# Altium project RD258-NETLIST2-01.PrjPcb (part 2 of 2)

## Sheet 9.SchDoc
size 420 x 297 mm
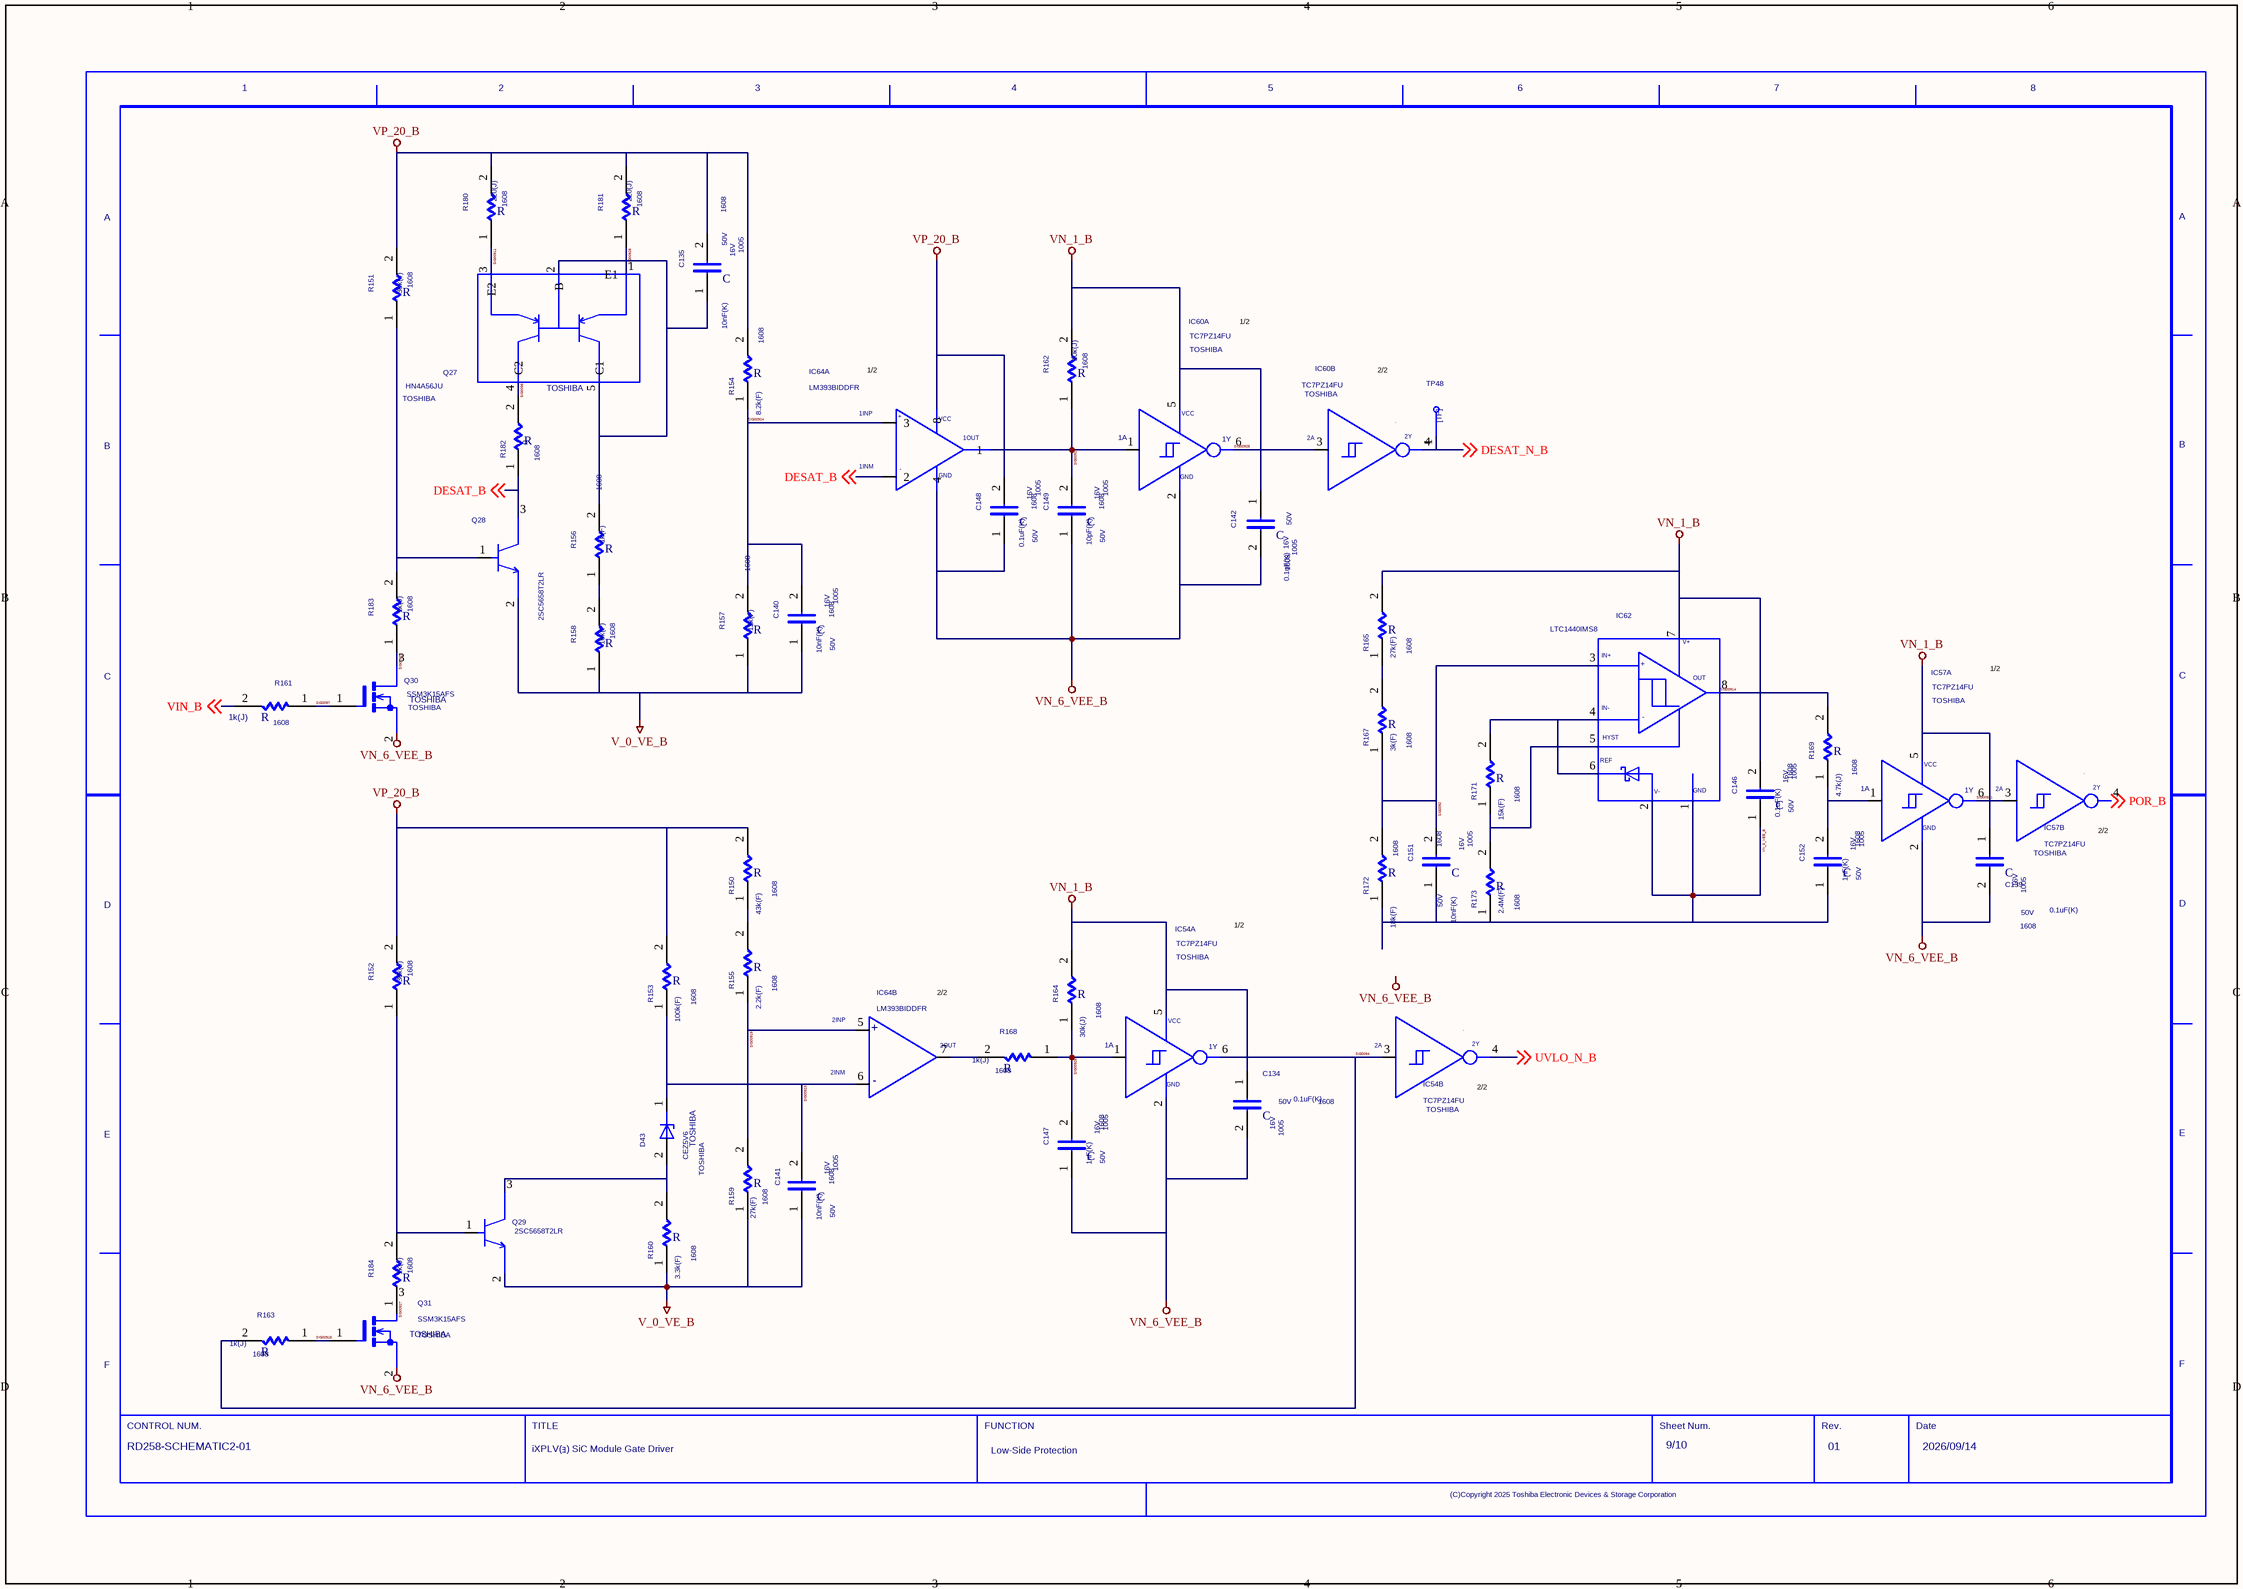
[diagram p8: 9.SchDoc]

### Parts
(Parts that share a designator on the sheet are numbered #1, #2 ... from top to bottom, then left to right.)
C134  VAL1: 0.1uF(K)  CODE: 1005  VOLTAGE: 16V  SIZECODESMD: 1608  VAL2: 50V  (hidden comment: C)
C135  VAL1: 10nF(K)  CODE: 1005  VOLTAGE: 16V  SIZECODESMD: 1608  VAL2: 50V  (hidden comment: C)
C139  VAL1: 0.1uF(K)  CODE: 1005  VOLTAGE: 16V  SIZECODESMD: 1608  VAL2: 50V  (hidden comment: C)
C140  VAL1: 10nF(K)  CODE: 1005  VOLTAGE: 16V  SIZECODESMD: 1608  VAL2: 50V  (hidden comment: C)
C141  VAL1: 10nF(K)  CODE: 1005  VOLTAGE: 16V  SIZECODESMD: 1608  VAL2: 50V  (hidden comment: C)
C142  VAL1: 0.1uF(K)  CODE: 1005  VOLTAGE: 16V  SIZECODESMD: 1608  VAL2: 50V  (hidden comment: C)
C146  VAL1: 0.1uF(K)  CODE: 1005  VOLTAGE: 16V  SIZECODESMD: 1608  VAL2: 50V  (hidden comment: C)
C147  VAL1: 1nF(K)  CODE: 1005  VOLTAGE: 16V  SIZECODESMD: 1608  VAL2: 50V  (hidden comment: C)
C148  VAL1: 0.1uF(K)  CODE: 1005  VOLTAGE: 16V  SIZECODESMD: 1608  VAL2: 50V  (hidden comment: C)
C149  VAL1: 10pF(K)  CODE: 1005  VOLTAGE: 16V  SIZECODESMD: 1608  VAL2: 50V  (hidden comment: C)
C151  VAL1: 10nF(K)  CODE: 1005  VOLTAGE: 16V  SIZECODESMD: 1608  VAL2: 50V  (hidden comment: C)
C152  VAL1: 1nF(K)  CODE: 1005  VOLTAGE: 16V  SIZECODESMD: 1608  VAL2: 50V  (hidden comment: C)
D43  VENDOR: TOSHIBA  (hidden comment: CEZ5V6)
IC54  USERCOMPTEXT3: TOSHIBA  VAL3: TC7PZ14FU  (hidden comment: TC7PZ17FU)  (parts A,B of 2)
IC57  USERCOMPTEXT3: TOSHIBA  VAL3: TC7PZ14FU  (hidden comment: TC7PZ17FU)  (parts A,B of 2)
IC60  USERCOMPTEXT3: TOSHIBA  VAL3: TC7PZ14FU  (hidden comment: TC7PZ17FU)  (parts A,B of 2)
IC62  VAL3: LTC1440IMS8  (hidden comment: LTC1440IS8)
IC64  VAL3: LM393BIDDFR  (hidden comment: LM393B_2)  (parts A,B of 2)
Q27  VENDOR: TOSHIBA  (hidden comment: HN4A56JU)
Q28  VAL3: 2SC5658T2LR  (hidden comment: 2SC5658J)
Q29  VAL3: 2SC5658T2LR  (hidden comment: 2SC5658J)
Q30  VENDOR: TOSHIBA  (hidden comment: SSM3K15AFS)
Q31  VENDOR: TOSHIBA  (hidden comment: SSM3K15AFS)
R150  VAL1: 43k(F)  SIZECODESMD: 1608  (hidden comment: R)
R151  VAL1: 30k(J)  SIZECODESMD: 1608  (hidden comment: R)
R152  VAL1: 30k(J)  SIZECODESMD: 1608  (hidden comment: R)
R153  VAL1: 100k(F)  SIZECODESMD: 1608  (hidden comment: R)
R154  VAL1: 8.2k(F)  SIZECODESMD: 1608  (hidden comment: R)
R155  VAL1: 2.2k(F)  SIZECODESMD: 1608  (hidden comment: R)
R156  VAL1: 1k(F)  SIZECODESMD: 1608  (hidden comment: R)
R157  VAL1: 12k(F)  SIZECODESMD: 1608  (hidden comment: R)
R158  VAL1: 10k(F)  SIZECODESMD: 1608  (hidden comment: R)
R159  VAL1: 27k(F)  SIZECODESMD: 1608  (hidden comment: R)
R160  VAL1: 3.3k(F)  SIZECODESMD: 1608  (hidden comment: R)
R161  VAL1: 1k(J)  SIZECODESMD: 1608  (hidden comment: R)
R162  VAL1: 30k(J)  SIZECODESMD: 1608  (hidden comment: R)
R163  VAL1: 1k(J)  SIZECODESMD: 1608  (hidden comment: R)
R164  VAL1: 30k(J)  SIZECODESMD: 1608  (hidden comment: R)
R165  VAL1: 27k(F)  SIZECODESMD: 1608  (hidden comment: R)
R167  VAL1: 3k(F)  SIZECODESMD: 1608  (hidden comment: R)
R168  VAL1: 1k(J)  SIZECODESMD: 1608  (hidden comment: R)
R169  VAL1: 4.7k(J)  SIZECODESMD: 1608  (hidden comment: R)
R171  VAL1: 15k(F)  SIZECODESMD: 1608  (hidden comment: R)
R172  VAL1: 18k(F)  SIZECODESMD: 1608  (hidden comment: R)
R173  VAL1: 2.4M(F)  SIZECODESMD: 1608  (hidden comment: R)
R180  VAL1: 220(J)  SIZECODESMD: 1608  (hidden comment: R)
R181  VAL1: 220(J)  SIZECODESMD: 1608  (hidden comment: R)
R182  VAL1: 0  SIZECODESMD: 1608  (hidden comment: R)
R183  VAL1: 1k(J)  SIZECODESMD: 1608  (hidden comment: R)
R184  VAL1: 1k(J)  SIZECODESMD: 1608  (hidden comment: R)
TP48  TP  (value not drawn)
U?#9  DATE: 2026/09/14  DRAWINGNUMBER: RD258-SCHEMATIC2-01  TITLE: iXPLV(ｮ) SiC Module Gate Driver  FUNCTION: Low-Side Protection  SHEETNUMBER: 9/10  REVISION: 01  (hidden comment: WAKU_DEF100)

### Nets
V_0_VE_B: C140.1 C141.1 Q28.2(E) Q29.2(E) R157.1 R158.1 R159.1 R160.1
VN_1_B: C134.1 C139.1 C142.1 C146.2 IC54.5 IC57.5 IC60.5 IC62.7(V+) R162.2 R164.2 R165.2
VN_6_VEE_B: C134.2 C139.2 C142.2 C146.1 C147.1 C148.1 C149.1 C151.1 C152.1 IC54.2 IC57.2 IC60.2 IC62.1(GND) IC62.2(V-) IC64.4 Q30.2(S) Q31.2(S) R172.1 R173.1
VP_20_B: C135.2 C148.2 IC64.8 R150.2 R151.2 R152.2 R153.2 R154.2 R180.2 R181.2
DESAT_B: IC64.2 Q28.3(C) R182.1 ; off-sheet DESAT_B
DESAT_N_B: IC60.4 TP48.1 ; off-sheet DESAT_N_B
POR_B: IC57.4 ; off-sheet POR_B
SIG0091: C149.2 IC60.1 IC64.1 R162.1
SIG0092: C151.2 IC62.3(IN+) R167.1 R172.2
SIG0093: Q29.1(B) R152.1 R184.2
SIG0094: IC54.3 IC54.6 R163.2
SIG0095: IC64.7 R168.2
SIG0096: Q27.4(C2) R182.2
SIG0097: Q30.1(G) R161.1
SIG0098: IC62.4(IN-) IC62.6(REF) R171.2
SIG0099: R165.1 R167.2
SIG00910: Q28.1(B) R151.1 R183.2
SIG00911: Q27.3(E2) R180.1
SIG00912: IC62.5(HYST) R171.1 R173.2
SIG00913: D43.2(A) Q29.3(C) R160.2
SIG00914: IC62.8(OUT) R169.2
SIG00915: Q31.1(G) R163.1
SIG00916: R156.1 R158.2
SIG00917: C135.1 Q27.2(B) Q27.5(C1) R156.2
SIG00918: R150.1 R155.2
SIG00919: IC64.5 R155.1 R159.2
SIG00920: C152.2 IC57.1 R169.1
SIG00921: IC57.3 IC57.6
SIG00922: Q30.3(D) R183.1
SIG00923: C141.2 D43.1(C) IC64.6 R153.1
SIG00924: C140.2 IC64.3 R154.1 R157.2
SIG00925: IC60.3 IC60.6
SIG00926: C147.2 IC54.1 R164.1 R168.1
SIG00927: Q31.3(D) R184.1
SIG00928: Q27.1(E1) R181.1
UVLO_N_B: IC54.4 ; off-sheet UVLO_N_B
VIN_B: R161.2 ; off-sheet VIN_B

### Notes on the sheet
- 1/2
- (near IC64) 1/2
- 2/2
- (near IC57) 2/2
- (near IC64) 2/2
- (near IC54) 2/2
- Labels drawn without touching a wire or pin: VN_6_VEE_B

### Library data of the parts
C134 C135 C139-C142 C146-C149 C151 C152 = C: TIME: 08:48:12; UPDATEUSER: HP_Z8_KEYSHOT; SAVECOUNT: 2; TC1: 0; PSPICETEMPLATE: C^@REFDES %1 %2 ?TOLERANCE¦C^@REFDES¦ @VALUE ?IC/IC=@IC/ TC=@TC1,@TC2 ?TOLERANCE¦\n.model C^@REFDES CAP C=1 DEV=@TOLERANCE% TC1=@TC1 TC2=@TC2 VC1=@VC1 VC2=@VC2¦; ORIGINALSYMBOLORIGIN: (0,0); INSTANCENAME: INS2265204
D43 = CEZ5V6: TIME: 14:49:55; UPDATEUSER: fukuda-y; UPDATETIME: 08:16:22; SAVECOUNT: 9; SAVEAREA0: -4630,-153,17114,13055; PSPICETEMPLATE: X^@REFDES %C %A @MODEL; ORIGINALSYMBOLORIGIN: (0,0); INSTANCENAME: INS2265024
IC54 IC57 = TC7PZ14FU_2: TIME: 11:55:01; UPDATEUSER: t5459927; UPDATETIME: 19:09:34; SAVECOUNT: 7; SPLIT_INST: TRUE; PSPICETEMPLATE: X^@REFDES %1A %GND %2A %2Y %VCC %1Y @MODEL; SWAP_INFO: (S1+S2); OriginalSymbolOrigin: (5080,15240); CaptureCellPackProp: TC7PZ14FU_2A; FUNCN: TC7PZ14FU_1; INSTANCENAME: INS2254016
IC60 = TC7PZ14FU_2: TIME: 11:55:01; UPDATEUSER: t5459927; UPDATETIME: 19:09:34; SAVECOUNT: 7; SPLIT_INST: TRUE; PSPICETEMPLATE: X^@REFDES %1A %GND %2A %2Y %VCC %1Y @MODEL; SWAP_INFO: (S1+S2); OriginalSymbolOrigin: (5080,15240); CaptureCellPackProp: TC7PZ14FU_2A; FUNCN: TC7PZ17FU_1; INSTANCENAME: INS2254016
IC62 = LTC1440IS8: TIME: 08:48:16; UPDATEUSER: t5459927; UPDATETIME: 17:22:21; SAVECOUNT: 4; PSPICETEMPLATE: X^@REFDES %GND %V- %IN+ %IN- %HYST %REF %V+ %OUT @MODEL; OriginalSymbolOrigin: (0,0); INSTANCENAME: INS2264292
IC64 = LM393B_2: TIME: 08:48:12; UPDATEUSER: t5459927; UPDATETIME: 19:15:42; SAVECOUNT: 5; SPLIT_INST: TRUE; PSPICETEMPLATE: X^@REFDES %INN %VSS %INP %OUT %VDD @MODEL; COMP: LM393B; VENDOR: TI; SWAP_INFO: (S1+S2); OriginalSymbolOrigin: (2540,0); CaptureCellPackProp: LM393B_2A; FUNCN: LM393B_1; INSTANCENAME: INS2264892
Q27 = HN4A56JU: TIME: 08:48:13; UPDATEUSER: HP_Z8_KEYSHOT; SAVECOUNT: 2; PSPICETEMPLATE: X^@REFDES %B1 %E %B2 %C2 %C1 @MODEL; OriginalSymbolOrigin: (0,0); INSTANCENAME: INS2265108
Q28 = 2SC5658J: TIME: 09:39:04; UPDATEUSER: 19910145; UPDATETIME: 15:12:10; SAVECOUNT: 8; VENDOR: ROHM; SAVEAREA0: -6194,-158,18648,15662; PSPICETEMPLATE: X^@REFDES %C %B %E @MODEL; ORIGINALSYMBOLORIGIN: (0,0); INSTANCENAME: INS2264212
Q29 = 2SC5658J: TIME: 09:39:04; UPDATEUSER: 19910145; UPDATETIME: 15:12:10; SAVECOUNT: 8; VENDOR: ROHM; SAVEAREA0: -6194,-158,18648,15662; PSPICETEMPLATE: X^@REFDES %C %B %E @MODEL; ORIGINALSYMBOLORIGIN: (0,0); INSTANCENAME: INS2264508
Q30 = SSM3K15AFS: TIME: 08:48:15; UPDATEUSER: HP_Z8_KEYSHOT; SAVECOUNT: 2; ORIGINALSYMBOLORIGIN: (0,0); PSPICETEMPLATE: X^@REFDES %D %G %S @MODEL; INSTANCENAME: INS2265300
Q31 = SSM3K15AFS: TIME: 08:48:15; UPDATEUSER: HP_Z8_KEYSHOT; SAVECOUNT: 2; ORIGINALSYMBOLORIGIN: (0,0); PSPICETEMPLATE: X^@REFDES %D %G %S @MODEL; INSTANCENAME: INS2264184
R150-R165 R167-R169 R171-R173 R180 R181 R183 R184 = R: TIME: 08:48:13; UPDATEUSER: HP_Z8_KEYSHOT; SAVECOUNT: 2; VAL2: 100mW; TC1: 0; PSPICETEMPLATE: R^@REFDES %1 %2 ?TOLERANCE¦R^@REFDES¦ @VALUE TC=@TC1,@TC2 ?TOLERANCE¦\n.model R^@REFDES RES R=1 DEV=@TOLERANCE% TC1=@TC1 TC2=@TC2¦; ORIGINALSYMBOLORIGIN: (0,0); INSTANCENAME: INS2263832
R182 = R: TIME: 08:48:13; UPDATEUSER: HP_Z8_KEYSHOT; SAVECOUNT: 2; VAL2: 0.125; PSPICETEMPLATE: R^@REFDES %1 %2 ?TOLERANCE¦R^@REFDES¦ @VALUE TC=@TC1,@TC2 ?TOLERANCE¦\n.model R^@REFDES RES R=1 DEV=@TOLERANCE% TC1=@TC1 TC2=@TC2¦; ORIGINALSYMBOLORIGIN: (0,0); INSTANCENAME: INS2264424
TP48 = TP: TIME: 16:12:21; UPDATEUSER: fukuda-y; UPDATETIME: 16:18:11; SAVECOUNT: 2; SAVEAREA0: -242,-92,12810,7836; ORIGINALSYMBOLORIGIN: (0,0); INSTANCENAME: INS2264820
U?#9 = WAKU_DEF100: PLOTTIME: HH:MM; SAVEAREA0: -63393,-16950,474261,314592; TIME: 14:30:25; UPDATEUSER: t5459927; UPDATETIME: 14:59:41; SAVECOUNT: 4; OriginalSymbolOrigin: (10160,284480); SHTSAVECOUNT: 27

## Sheet 10.SchDoc
size 420 x 297 mm
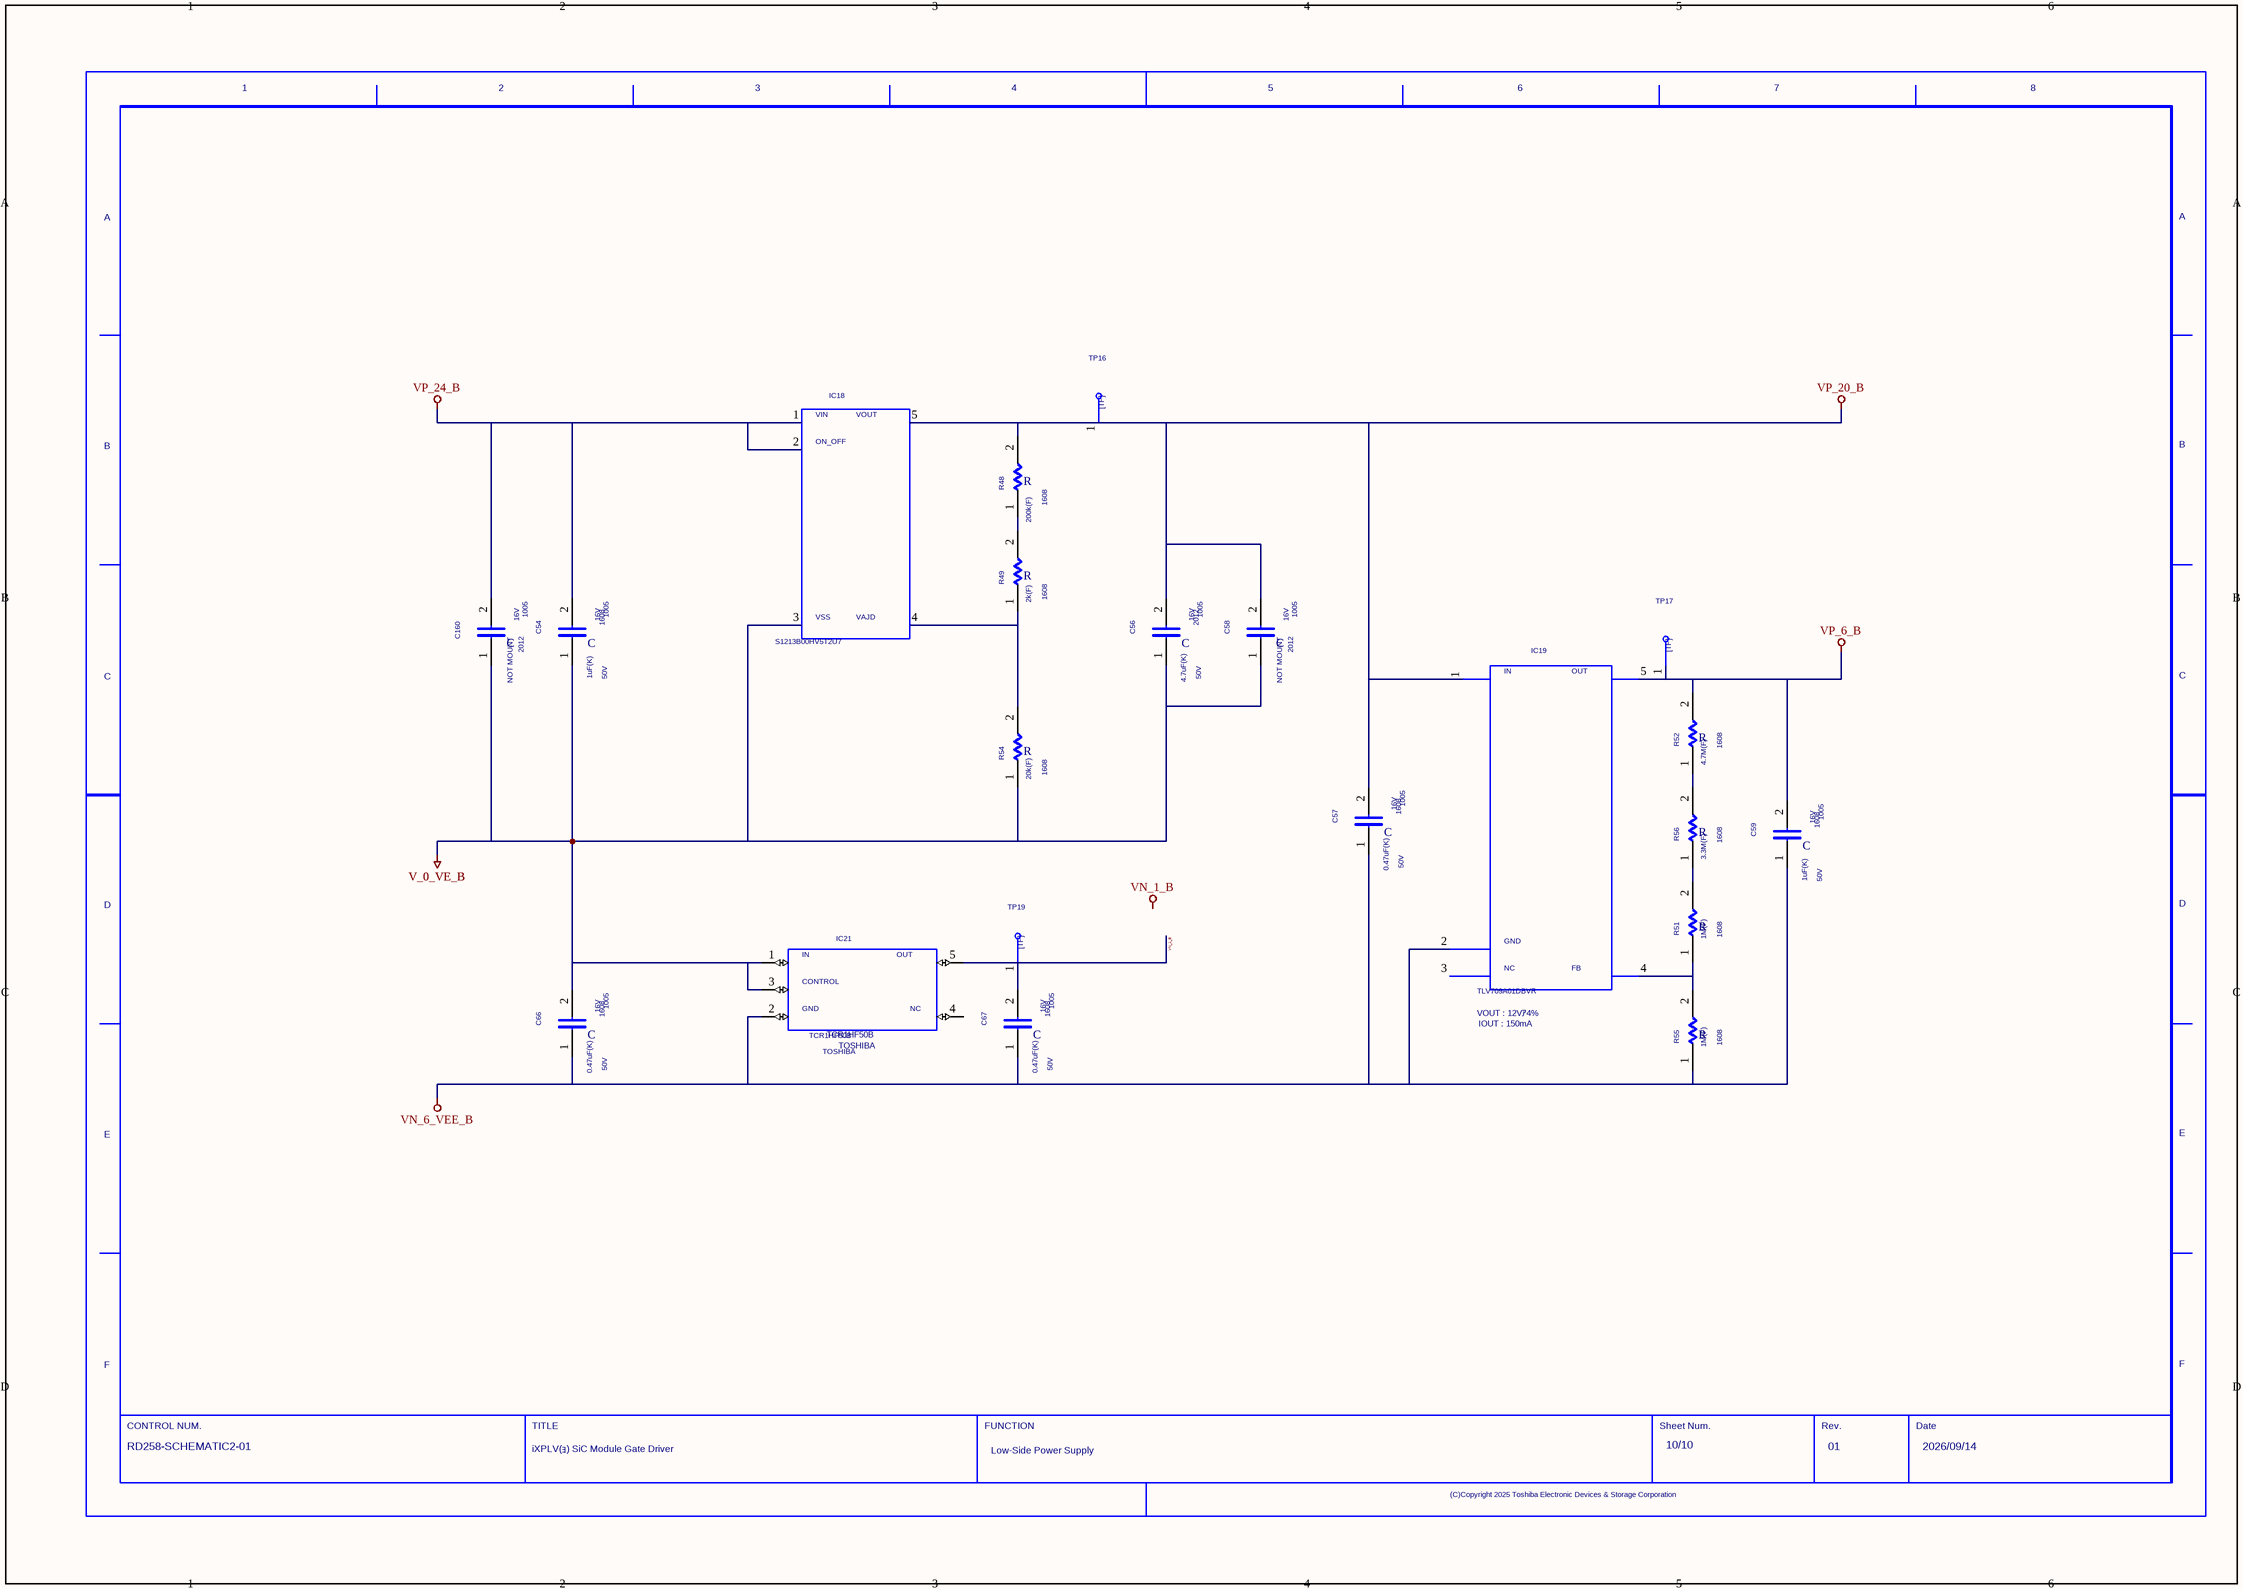
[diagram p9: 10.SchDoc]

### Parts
(Parts that share a designator on the sheet are numbered #1, #2 ... from top to bottom, then left to right.)
C54  VAL1: 1uF(K)  CODE: 1005  VOLTAGE: 16V  SIZECODESMD: 1608  VAL2: 50V  (hidden comment: C)
C56  VAL1: 4.7uF(K)  CODE: 1005  VOLTAGE: 16V  SIZECODESMD: 2012  VAL2: 50V  (hidden comment: C)
C57  VAL1: 0.47uF(K)  CODE: 1005  VOLTAGE: 16V  SIZECODESMD: 1608  VAL2: 50V  (hidden comment: C)
C58  CODE: 1005  VOLTAGE: 16V  NOTMOUNT: NOT MOUNT  SIZECODESMD: 2012  (hidden comment: C)
C59  VAL1: 1uF(K)  CODE: 1005  VOLTAGE: 16V  SIZECODESMD: 1608  VAL2: 50V  (hidden comment: C)
C66  VAL1: 0.47uF(K)  CODE: 1005  VOLTAGE: 16V  SIZECODESMD: 1608  VAL2: 50V  (hidden comment: C)
C67  VAL1: 0.47uF(K)  CODE: 1005  VOLTAGE: 16V  SIZECODESMD: 1608  VAL2: 50V  (hidden comment: C)
C160  CODE: 1005  VOLTAGE: 16V  NOTMOUNT: NOT MOUNT  SIZECODESMD: 2012  (hidden comment: C)
IC18  S1213B00HV5T2U7
IC19  NC: VOUT : 12Vｱ4%  CLASS: IOUT : 150mA  VAL3: TLV709A01DBVR  (hidden comment: TLV709)
IC21  TCR1HF50B  VENDOR: TOSHIBA
R48  VAL1: 200k(F)  SIZECODESMD: 1608  (hidden comment: R)
R49  VAL1: 2k(F)  SIZECODESMD: 1608  (hidden comment: R)
R51  VAL1: 1M(F)  SIZECODESMD: 1608  (hidden comment: R)
R52  VAL1: 4.7M(F)  SIZECODESMD: 1608  (hidden comment: R)
R54  VAL1: 20k(F)  SIZECODESMD: 1608  (hidden comment: R)
R55  VAL1: 1M(F)  SIZECODESMD: 1608  (hidden comment: R)
R56  VAL1: 3.3M(F)  SIZECODESMD: 1608  (hidden comment: R)
TP16  TP  (value not drawn)
TP17  TP  (value not drawn)
TP19  TP  (value not drawn)
U?#10  DATE: 2026/09/14  DRAWINGNUMBER: RD258-SCHEMATIC2-01  TITLE: iXPLV(ｮ) SiC Module Gate Driver  FUNCTION: Low-Side Power Supply  SHEETNUMBER: 10/10  REVISION: 01  (hidden comment: WAKU_DEF100)

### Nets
V_0_VE_B: C54.1 C56.1 C58.1 C66.2 C160.1 IC18.3 IC21.1 IC21.3 R54.1
VN_1_B: C67.2 IC21.5 TP19.1
VN_6_VEE_B: C57.1 C59.1 C66.1 C67.1 IC19.2 IC21.2 R55.1
VP_6_B: C59.2 IC19.5 R52.2 TP17.1
VP_20_B: C56.2 C57.2 C58.2 IC18.5 IC19.1 R48.2 TP16.1
VP_24_B: C54.2 C160.2 IC18.1 IC18.2
SIG0101: IC18.4 R49.1 R54.2
SIG0102: R52.1 R56.2
SIG0103: IC19.4 R51.1 R55.2
SIG0104: R48.1 R49.2
SIG0105: R51.2 R56.1

Not connected (* = marked no-connect by the designer): IC19 3; IC21 4

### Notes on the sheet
- Labels drawn without touching a wire or pin: VN_1_B

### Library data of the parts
C54 C56-C59 C66 C67 C160 = C: TIME: 08:48:12; UPDATEUSER: HP_Z8_KEYSHOT; SAVECOUNT: 2; TC1: 0; PSPICETEMPLATE: C^@REFDES %1 %2 ?TOLERANCE¦C^@REFDES¦ @VALUE ?IC/IC=@IC/ TC=@TC1,@TC2 ?TOLERANCE¦\n.model C^@REFDES CAP C=1 DEV=@TOLERANCE% TC1=@TC1 TC2=@TC2 VC1=@VC1 VC2=@VC2¦; ORIGINALSYMBOLORIGIN: (0,0); INSTANCENAME: INS2266227
IC18 = S1213B00HV5T2U7: TIME: 08:48:13; UPDATEUSER: t5459927; UPDATETIME: 09:48:38; SAVECOUNT: 7; PSPICETEMPLATE: X^@REFDES %ADJUST %OUTPUT %INPUT @MODEL; OriginalSymbolOrigin: (0,0); INSTANCENAME: INS2266489
IC19 = TLV709: TIME: 08:48:16; UPDATEUSER: t5459927; UPDATETIME: 10:01:49; SAVECOUNT: 5; PSPICETEMPLATE: X^@REFDES %IN %GND %NC %FB %OUT @MODEL; OriginalSymbolOrigin: (0,0); INSTANCENAME: INS2266385
IC21 = TCR1HF50B: TIME: 11:54:59; UPDATEUSER: t5459927; UPDATETIME: 10:27:35; SAVECOUNT: 4; PSPICETEMPLATE: X^@REFDES %IN %GND %CONTROL %NC %OUT @MODEL; OriginalSymbolOrigin: (-2540,0); INSTANCENAME: INS2266087
R48 R49 R51 R52 R54-R56 = R: TIME: 08:48:13; UPDATEUSER: HP_Z8_KEYSHOT; SAVECOUNT: 2; VAL2: 100mW; TC1: 0; PSPICETEMPLATE: R^@REFDES %1 %2 ?TOLERANCE¦R^@REFDES¦ @VALUE TC=@TC1,@TC2 ?TOLERANCE¦\n.model R^@REFDES RES R=1 DEV=@TOLERANCE% TC1=@TC1 TC2=@TC2¦; ORIGINALSYMBOLORIGIN: (0,0); INSTANCENAME: INS2266059
TP16 = TP: TIME: 16:12:21; UPDATEUSER: fukuda-y; UPDATETIME: 16:18:11; SAVECOUNT: 2; SAVEAREA0: -242,-92,12810,7836; ORIGINALSYMBOLORIGIN: (0,0); INSTANCENAME: INS2266317
TP17 = TP: TIME: 16:12:21; UPDATEUSER: fukuda-y; UPDATETIME: 16:18:11; SAVECOUNT: 2; SAVEAREA0: -242,-92,12810,7836; ORIGINALSYMBOLORIGIN: (0,0); INSTANCENAME: INS2266305
TP19 = TP: TIME: 16:12:21; UPDATEUSER: fukuda-y; UPDATETIME: 16:18:11; SAVECOUNT: 2; SAVEAREA0: -242,-92,12810,7836; ORIGINALSYMBOLORIGIN: (0,0); INSTANCENAME: INS2266293
U?#10 = WAKU_DEF100: PLOTTIME: HH:MM; SAVEAREA0: -63393,-16950,474261,314592; TIME: 14:30:25; UPDATEUSER: t5459927; UPDATETIME: 14:21:48; SAVECOUNT: 4; OriginalSymbolOrigin: (10160,284480); SHTSAVECOUNT: 22

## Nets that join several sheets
V_0_VE_A: 1 (CN2.3 CN2.4), 2 (13 pins), 4 (8 pins), 5 (9 pins)
V_0_VE_B: 6 (CN3.3 CN3.4), 7 (13 pins), 9 (8 pins), 10 (9 pins)
VN_1_A: 1 (15 pins), 2 (6 pins), 3 (15 pins), 4 (11 pins), 5 (C48.2 IC17.5 TP14.1)
VN_1_B: 6 (15 pins), 7 (6 pins), 8 (15 pins), 9 (11 pins), 10 (C67.2 IC21.5 TP19.1)
VN_6_VEE_A: 1 (17 pins), 2 (15 pins), 3 (28 pins), 4 (19 pins), 5 (7 pins)
VN_6_VEE_B: 6 (17 pins), 7 (15 pins), 8 (28 pins), 9 (19 pins), 10 (7 pins)
VP_6_A: 2 (C95.2 IC35.1), 5 (C40.2 IC15.5 R31.2 TP12.1)
VP_6_B: 7 (C107.2 IC39.1), 10 (C59.2 IC19.5 R52.2 TP17.1)
VP_20_A: 2 (9 pins), 4 (10 pins), 5 (7 pins)
VP_20_B: 7 (9 pins), 9 (10 pins), 10 (7 pins)
VP_24_A: 1 (CN2.1 CN2.2), 5 (C35.2 C159.2 IC14.1 IC14.2)
VP_24_B: 6 (CN3.1 CN3.2), 10 (C54.2 C160.2 IC18.1 IC18.2)
DESAT_A: 2 (6 pins), 4 (IC51.2 Q22.3 R177.1)
DESAT_B: 7 (6 pins), 9 (IC64.2 Q28.3 R182.1)
DESAT_N_A: 1 (IC49.5), 4 (IC48.4 TP46.1)
DESAT_N_B: 6 (IC61.5), 9 (IC60.4 TP48.1)
GCLP_EN_A: 1 (IC46.3), 3 (IC25.1 IC27.2)
GCLP_EN_B: 6 (IC58.3), 8 (IC31.1 IC33.2)
POR_A: 1 (IC46.2 IC49.1), 4 (IC45.4)
POR_B: 6 (IC58.2 IC61.1), 9 (IC57.4)
PRED_EN_A: 1 (5 pins), 2 (C155.1 IC35.6)
PRED_EN_B: 6 (5 pins), 7 (C158.1 IC39.6)
STO_VMOS_A: 1 (IC44.6), 3 (R104.1 TP43.1)
STO_VMOS_B: 6 (IC56.6), 8 (R124.1 TP44.1)
UVLO_N_A: 1 (IC46.1), 4 (IC42.4)
UVLO_N_B: 6 (IC58.1), 9 (IC54.4)
VGATE_A: 2 (13 pins), 3 (6 pins)
VGATE_B: 7 (13 pins), 8 (6 pins)
VIN_A: 1 (IC44.3 IC47.7), 2 (IC36.1), 4 (R136.2)
VIN_B: 6 (IC56.3 IC59.7), 7 (IC40.1), 9 (R161.2)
